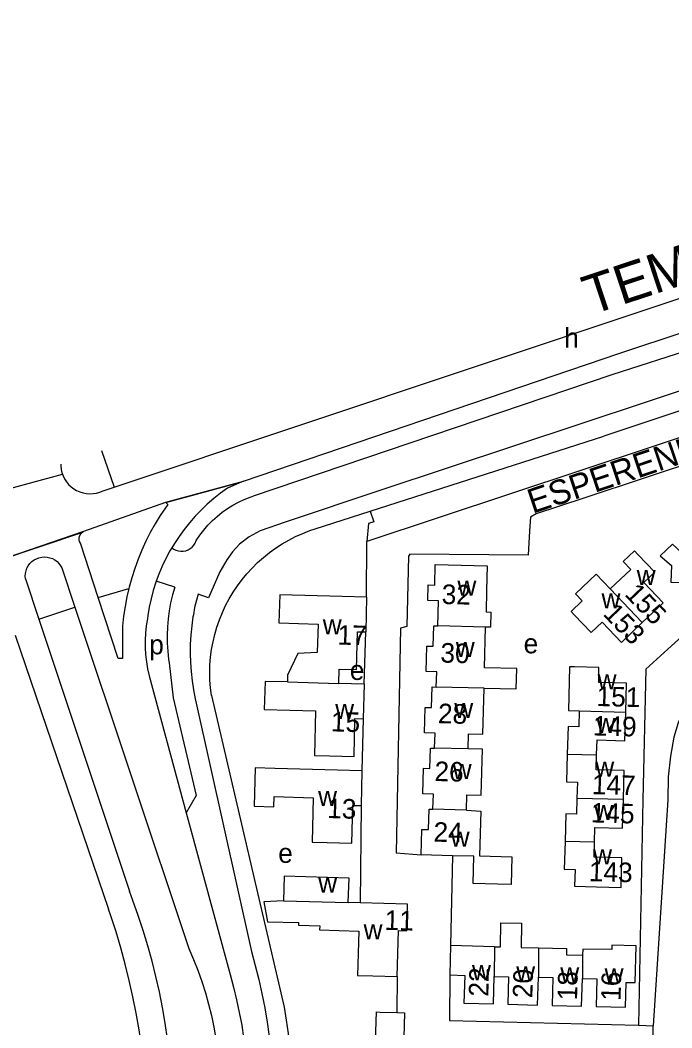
# Model space of a CAD drawing. Extents: x 161936 to 163647, y 386450 to 388633.
# Drawn here: x 162199.4 to 162332.5, y 388398.4 to 388604.3 of the extents above; entities that cross this region are included whole.
import ezdxf

# ---------------------------------------------------------------- set-up
doc = ezdxf.new("R2010")
doc.units = 0
for name, color, linetype in [('BLT_Basislijn', 7, 'Continuous'), ('BLT_Bebouwing', 7, 'Continuous'), ('BLT_Centroide', 7, 'Continuous'), ('BLT_Huisnummer', 7, 'Continuous'), ('BLT_Huisnummer_ tussenligend', 7, 'Continuous'), ('BLT_Onderverdeling_panden', 7, 'Continuous'), ('BLT_Straatnaam', 7, 'Continuous'), ('BLT_Straatnaam_hoofdweg', 7, 'Continuous'), ('BLT_Vlakafsluiter', 7, 'Continuous')]:
    doc.layers.add(name, color=color, linetype=linetype)

msp = doc.modelspace()

# ---------------------------------------------------------------- linework, layer by layer
at = {"layer": 'BLT_Basislijn'}
for p, q in [((162417.3, 388562.99), (162320.24, 388531.86)), ((162320.24, 388531.86), (162247, 388507.07)), ((162270.93, 388504.03), (162318.61, 388519.35)), ((162216.04, 388516.41), (162218.65, 388508.94)), ((162216.15, 388508.1), (162218.65, 388508.94)), ((162273.31, 388508.35), (162253.51, 388501.78)), ((162259.69, 388500.42), (162270.93, 388504.03)), ((162215.37, 388486.34), (162211.74, 388497.46)), ((162270.18, 388486.44), (162270.23, 388497.84)), ((162207.93, 388492.42), (162210.6, 388484.42)), ((162200.52, 388490.16), (162203.24, 388481.96)), ((162215.37, 388486.34), (162221.63, 388488.23)), ((162230.98, 388488.5), (162227.22, 388489.69)), ((162203.24, 388481.96), (162210.6, 388484.42)), ((162210.6, 388484.42), (162233.9, 388414.65)), ((162203.24, 388481.96), (162221.73, 388426.34)), ((162198.38, 388478.67), (162217.49, 388422.65)), ((162269.7, 388468.68), (162270.01, 388479.33)), ((162229.85, 388473.02), (162230.69, 388465.88)), ((162225.77, 388470.37), (162233.35, 388442.37)), ((162238.48, 388466.33), (162253.34, 388402.63)), ((162235.4, 388464.79), (162246.64, 388414.02)), ((162269.5, 388461.6), (162269.23, 388450.96)), ((162331.69, 388444.99), (162328.69, 388398.84)), ((162269.06, 388443.84), (162268.87, 388423.97)), ((162233.35, 388442.37), (162242.29, 388409.3)), ((162287.74, 388433.61), (162287.33, 388415.23)), ((162276.44, 388408.91), (162276.34, 388401.56)), ((162325.67, 388399), (162328.69, 388398.84)), ((162328.55, 388389.95), (162328.69, 388398.84))]:
    msp.add_line(p, q, dxfattribs=at)
for points in [[(162245.01, 388510.15), (162321.69, 388536.21), (162403.77, 388563.49), (162420.12, 388569.86), (162440.47, 388580.95), (162451.05, 388585.71), (162460.59, 388590.61), (162470.65, 388596.83), (162481.66, 388604.34)], [(162218.65, 388508.94), (162366.2, 388558.22), (162401.08, 388569.64)], [(162447.07, 388563.49), (162414.11, 388552.89), (162414.48, 388551.26), (162318.61, 388519.35)], [(162408.33, 388553.19), (162273.31, 388508.35)], [(162420.21, 388534.15), (162419.72, 388536.07), (162387.4, 388536.71), (162270.23, 388497.84)], [(162351.5, 388518.91), (162314.5, 388506.68)], [(162207.72, 388513.6), (162207.72, 388513.24), (162207.8, 388512.55), (162207.96, 388511.88), (162208.07, 388511.55)], [(162208.07, 388511.55), (162208.19, 388511.23), (162208.5, 388510.61), (162208.87, 388510.02), (162209.32, 388509.49), (162209.81, 388509.01), (162210.37, 388508.59), (162210.96, 388508.24), (162211.59, 388507.96), (162212.26, 388507.76), (162212.93, 388507.63), (162213.62, 388507.58), (162214.32, 388507.61), (162215, 388507.72), (162215.67, 388507.91), (162216.15, 388508.1)], [(162244.71, 388510.02), (162241.74, 388508.7), (162240.32, 388507.68), (162238.95, 388506.59), (162237.63, 388505.44), (162236.36, 388504.23), (162235.14, 388502.96), (162233.99, 388501.64), (162232.9, 388500.27), (162231.87, 388498.85), (162230.91, 388497.38), (162230.39, 388496.51)], [(162245.01, 388510.15), (162244.71, 388510.02)], [(162235.4, 388498), (162236.13, 388499.09), (162236.92, 388500.14), (162237.77, 388501.13), (162238.68, 388502.07), (162239.65, 388502.95), (162240.67, 388503.77), (162241.74, 388504.53), (162242.85, 388505.22), (162244, 388505.84), (162245.19, 388506.39), (162246.41, 388506.87), (162247, 388507.07)], [(162314.5, 388506.68), (162304.79, 388503.47), (162303.65, 388502.79), (162303.44, 388500), (162303.15, 388495.01), (162279.02, 388495.2), (162278.7, 388494.79), (162278.38, 388480.46), (162277.09, 388480.11), (162276.21, 388434.19), (162281.34, 388433.78)], [(162212.45, 388499.89), (162229.15, 388505.84)], [(162229.19, 388505.8), (162229.6, 388505.38), (162228.02, 388503.12)], [(162229.15, 388505.84), (162229.19, 388505.8)], [(162228.02, 388503.12), (162226.98, 388501.41), (162226, 388499.66), (162225.1, 388497.86), (162224.27, 388496.04), (162223.51, 388494.18), (162222.82, 388492.3), (162222.21, 388490.38), (162221.68, 388488.45), (162221.63, 388488.23)], [(162270.93, 388504.03), (162271.64, 388501.83), (162270.59, 388501.51), (162270.23, 388497.84)], [(162253.51, 388501.78), (162248.43, 388500), (162246.16, 388498.78), (162244.19, 388497.26), (162242.82, 388495.7), (162241.65, 388494.04), (162240.17, 388491.59), (162237.87, 388486.3), (162235.77, 388487.08), (162235.41, 388485.84), (162235.06, 388484.35), (162234.79, 388482.84), (162234.72, 388482.39)], [(162211.74, 388497.46), (162211.57, 388497.78), (162211.47, 388498.13), (162211.46, 388498.49), (162211.52, 388498.84), (162211.66, 388499.18), (162211.87, 388499.47), (162212.14, 388499.71), (162212.21, 388499.75)], [(162212.21, 388499.75), (162212.45, 388499.89)], [(162238.48, 388466.33), (162238.29, 388467.89), (162238.18, 388469.46), (162238.14, 388471.03), (162238.19, 388472.61), (162238.32, 388474.18), (162238.52, 388475.74), (162238.81, 388477.29), (162239.17, 388478.82), (162239.61, 388480.33), (162240.13, 388481.82), (162240.72, 388483.28), (162241.38, 388484.7), (162242.12, 388486.09), (162242.93, 388487.45), (162243.8, 388488.75), (162244.74, 388490.02), (162245.74, 388491.23), (162246.8, 388492.39), (162247.92, 388493.5), (162249.1, 388494.55), (162250.33, 388495.53), (162251.6, 388496.46), (162252.92, 388497.31), (162254.28, 388498.1), (162255.68, 388498.82), (162257.12, 388499.47), (162258.59, 388500.04), (162259.69, 388500.42)], [(162230.39, 388496.51), (162230.01, 388495.88), (162229.19, 388494.33), (162228.43, 388492.75), (162227.75, 388491.13), (162227.22, 388489.69)], [(162230.39, 388496.51), (162230.8, 388496.23), (162231.25, 388496.02), (162231.74, 388495.88), (162232.24, 388495.82), (162232.74, 388495.84), (162233.24, 388495.93), (162233.71, 388496.11), (162234.15, 388496.36), (162234.55, 388496.67), (162234.89, 388497.04), (162235.17, 388497.46), (162235.4, 388498)], [(162200.52, 388490.16), (162200.48, 388490.72), (162200.51, 388491.28), (162200.63, 388491.82), (162200.82, 388492.35), (162201.09, 388492.84), (162201.42, 388493.29), (162201.81, 388493.69), (162202.26, 388494.03), (162202.75, 388494.3), (162203.27, 388494.49), (162203.82, 388494.62), (162204.37, 388494.66), (162204.93, 388494.62), (162205.48, 388494.5), (162206, 388494.31), (162206.5, 388494.05), (162206.95, 388493.71), (162207.34, 388493.32), (162207.68, 388492.87), (162207.93, 388492.42)], [(162221.63, 388488.23), (162221.23, 388486.49), (162220.85, 388484.52), (162220.55, 388482.54), (162220.33, 388480.49)], [(162227.22, 388489.69), (162227.15, 388489.49), (162226.62, 388487.82), (162226.16, 388486.12), (162225.79, 388484.41), (162225.49, 388482.68), (162225.4, 388482.02)], [(162230.98, 388488.5), (162230.52, 388486.9), (162230.15, 388485.29), (162229.85, 388483.65), (162229.64, 388482.01), (162229.5, 388480.35), (162229.44, 388478.69), (162229.46, 388477.03), (162229.57, 388475.37), (162229.75, 388473.72), (162229.85, 388473.02)], [(162220.33, 388480.49), (162220.33, 388473.93), (162219.43, 388473.93), (162215.37, 388486.34)], [(162225.4, 388482.02), (162225.16, 388480.57), (162225.01, 388479.11), (162224.94, 388477.64), (162224.95, 388476.17), (162225.04, 388474.7), (162225.2, 388473.24), (162225.45, 388471.79), (162225.77, 388470.37)], [(162234.72, 388482.39), (162234.45, 388480.55), (162234.27, 388478.69), (162234.16, 388476.82), (162234.13, 388474.95), (162234.18, 388473.09), (162234.32, 388471.22), (162234.53, 388469.36), (162234.82, 388467.52), (162235.19, 388465.69), (162235.4, 388464.79)], [(162363.21, 388479.21), (162336.14, 388479.83), (162331.7, 388475.81)], [(162331.7, 388475.81), (162327.16, 388471.71), (162326.61, 388445.04)], [(162363.89, 388473.57), (162351.28, 388473.57), (162346.78, 388472.82), (162343.16, 388471.29), (162339.91, 388468.94), (162337.35, 388466.34), (162335.18, 388463.53), (162333.83, 388460.74), (162332.91, 388457.81), (162332.21, 388453.97), (162331.73, 388449.73), (162331.69, 388444.99)], [(162230.69, 388465.88), (162235.4, 388445.93), (162233.35, 388442.37)], [(162326.61, 388445.04), (162325.67, 388399)], [(162229.94, 388392.92), (162229.54, 388396.14), (162229.06, 388399.36), (162228.51, 388402.57), (162227.87, 388405.76), (162227.16, 388408.93), (162226.37, 388412.09), (162225.5, 388415.22), (162224.55, 388418.33), (162223.53, 388421.42), (162222.43, 388424.48), (162221.73, 388426.34)], [(162224.63, 388391.27), (162224.21, 388394.66), (162223.7, 388398.05), (162223.11, 388401.43), (162222.45, 388404.79), (162221.7, 388408.13), (162220.88, 388411.46), (162219.98, 388414.76), (162219.01, 388418.05), (162217.95, 388421.31), (162217.49, 388422.65)], [(162233.9, 388414.65), (162234.85, 388412.43), (162235.73, 388410.19), (162236.53, 388407.91), (162237.25, 388405.61), (162237.9, 388403.28), (162238.47, 388400.94), (162238.97, 388398.58), (162239.38, 388396.2)], [(162246.64, 388414.02), (162247.44, 388411.17), (162248.16, 388408.31), (162248.8, 388405.42), (162249.37, 388402.52), (162249.86, 388399.6), (162250.27, 388396.67), (162250.59, 388393.74), (162250.84, 388390.79), (162251.01, 388387.84), (162251.1, 388384.88), (162251.11, 388381.93), (162251.04, 388378.97), (162250.99, 388377.76)], [(162242.29, 388409.3), (162243, 388406.76), (162243.63, 388404.18), (162244.18, 388401.6), (162244.66, 388398.99), (162245.05, 388396.38), (162245.37, 388393.75), (162245.61, 388391.11), (162245.77, 388388.47), (162245.84, 388385.82), (162245.84, 388383.18), (162245.76, 388380.53), (162245.6, 388377.89), (162245.37, 388375.4)], [(162287.17, 388409.25), (162287.1, 388399.94), (162325.67, 388399)], [(162253.34, 388402.63), (162253.78, 388399.98), (162254.15, 388397.31), (162254.43, 388394.64), (162254.63, 388391.95), (162254.75, 388389.27), (162254.79, 388386.58), (162254.78, 388385.78)]]:
    msp.add_lwpolyline(points, dxfattribs=at)
at = {"layer": 'BLT_Bebouwing'}
for p, q in [((162270.18, 388486.44), (162270.01, 388479.33)), ((162269.7, 388468.68), (162269.5, 388461.6)), ((162269.23, 388450.96), (162269.06, 388443.84)), ((162287.74, 388433.61), (162281.34, 388433.78)), ((162287.33, 388415.23), (162287.17, 388409.25)), ((162296.09, 388403.32), (162296.23, 388408.91)), ((162305.09, 388403.09), (162305.25, 388408.79)), ((162314.08, 388402.87), (162314.24, 388408.54))]:
    msp.add_line(p, q, dxfattribs=at)
for points in [[(162336.97, 388495.39), (162334.56, 388495.46), (162332.67, 388497.29), (162330.13, 388494.88), (162332.41, 388492.92), (162332.32, 388489.52), (162336.82, 388489.4)], [(162326.47, 388481.24), (162330.74, 388485.29), (162326.78, 388489.42), (162329, 388491.53), (162325.56, 388495.16), (162324.87, 388495.88), (162322.59, 388493.7), (162324.11, 388492.1), (162319.92, 388488.11)], [(162284.71, 388480.6), (162284.87, 388485.69), (162282.68, 388485.74), (162282.76, 388488.96), (162284.08, 388488.92), (162284.19, 388493.13), (162294.8, 388492.83), (162294.67, 388487.83), (162294.56, 388483.43), (162295.54, 388483.4), (162295.46, 388480.3), (162294.47, 388480.33)], [(162319.92, 388488.11), (162317.03, 388491.14), (162312.83, 388487.15), (162314.21, 388485.7), (162311.93, 388483.53), (162312.59, 388482.83), (162316.04, 388479.21), (162318.25, 388481.32), (162322.2, 388477.18), (162326.47, 388481.24)], [(162270.18, 388486.44), (162265.18, 388486.57), (162252.43, 388486.9), (162252.27, 388481.17), (162260.26, 388480.95), (162260.1, 388475.12), (162256.15, 388474.91), (162254.04, 388470.49), (162254, 388469.11)], [(162284.39, 388468.07), (162284.49, 388471.19), (162282.32, 388471.26), (162282.44, 388476.45), (162283.76, 388476.41), (162283.9, 388480.61), (162284.71, 388480.6)], [(162294.15, 388467.85), (162300.74, 388467.69), (162300.85, 388471.84), (162294.26, 388472), (162294.47, 388480.33)], [(162264.5, 388468.82), (162264.6, 388471.74), (162268.09, 388471.65), (162268.31, 388479.38), (162270.01, 388479.33)], [(162323.08, 388462.96), (162323.23, 388468.85), (162317.58, 388469.02), (162317.6, 388472.03), (162312.6, 388472.17), (162311.63, 388472.2), (162311.39, 388463.26), (162313.59, 388463.21)], [(162254, 388469.11), (162249.44, 388469.23), (162249.28, 388463.47), (162259.76, 388463.18), (162259.51, 388454.11), (162262.61, 388454.03), (162267.61, 388453.89), (162267.8, 388461.64), (162269.5, 388461.6)], [(162269.7, 388468.68), (162264.5, 388468.82)], [(162284.04, 388455.61), (162284.14, 388458.64), (162282, 388458.71), (162282.12, 388463.92), (162283.45, 388463.88), (162283.57, 388468.1), (162284.39, 388468.07)], [(162290.92, 388455.43), (162291, 388458.5), (162293.9, 388458.42), (162294.15, 388467.85)], [(162313.59, 388463.21), (162313.5, 388459.94), (162311.31, 388460), (162311.16, 388454.36)], [(162317.14, 388454.2), (162317.23, 388457.26), (162322.93, 388457.1), (162323.08, 388462.96)], [(162283.73, 388443.11), (162283.82, 388446.21), (162281.67, 388446.28), (162281.8, 388451.46), (162283.11, 388451.42), (162283.24, 388455.59), (162284.04, 388455.61)], [(162290.59, 388442.93), (162290.67, 388446.05), (162293.59, 388445.97), (162293.82, 388455.35), (162290.92, 388455.43)], [(162311.16, 388454.36), (162311.01, 388448.71), (162313.21, 388448.65), (162313.12, 388445.39)], [(162322.61, 388445.14), (162322.76, 388451.01), (162317.06, 388451.17), (162317.14, 388454.2)], [(162269.23, 388450.96), (162264.23, 388451.1), (162251.45, 388451.45), (162247.44, 388451.56), (162247.22, 388443.73), (162251.23, 388443.61), (162251.29, 388445.68), (162259.29, 388445.46), (162259.05, 388436.39), (162262.15, 388436.31), (162267.15, 388436.17), (162267.36, 388443.89), (162269.06, 388443.84)], [(162313.12, 388445.39), (162313.04, 388442.12), (162310.84, 388442.18), (162310.69, 388436.49)], [(162316.7, 388436.35), (162316.77, 388439.39), (162322.45, 388439.26), (162322.61, 388445.14)], [(162281.34, 388433.78), (162281.47, 388438.99), (162282.79, 388438.95), (162282.93, 388443.14), (162283.73, 388443.11)], [(162290.59, 388442.93), (162293.49, 388442.7), (162293.25, 388433.57), (162299.81, 388433.38), (162299.71, 388427.71), (162296.92, 388427.79), (162291.92, 388427.92), (162292.08, 388433.49), (162287.74, 388433.61)], [(162310.69, 388436.49), (162310.55, 388430.86), (162312.74, 388430.81), (162312.65, 388427.37), (162317.13, 388427.25), (162322.13, 388427.11), (162322.31, 388433.18), (162316.63, 388433.31), (162316.7, 388436.35)], [(162266.43, 388424.04), (162266.58, 388429.03), (162253.33, 388429.4), (162253.19, 388424.41)], [(162253.19, 388424.41), (162249.18, 388424.19), (162249.95, 388420.12), (162256.26, 388419.94), (162256.25, 388419.4), (162260.61, 388419.28), (162260.58, 388418.43), (162268.59, 388418.19), (162268.32, 388409.12), (162271.44, 388409.04), (162276.44, 388408.91)], [(162268.87, 388423.97), (162266.43, 388424.04)], [(162276.44, 388408.91), (162276.67, 388418.32), (162278.38, 388418.27), (162278.53, 388423.7), (162268.87, 388423.97)], [(162296.3, 388415), (162297.49, 388414.97), (162297.61, 388419.9), (162301.83, 388419.8), (162301.71, 388414.87), (162305.28, 388414.78)], [(162296.3, 388415), (162287.33, 388415.23)], [(162305.28, 388414.78), (162311.01, 388414.62), (162310.98, 388413.35), (162314.28, 388413.28)], [(162314.24, 388408.54), (162317.18, 388408.45), (162317.02, 388402.78), (162323.07, 388402.63), (162323.2, 388407.73), (162325, 388407.68), (162325.2, 388415.18), (162320.25, 388415.31), (162320.22, 388414.41), (162314.31, 388414.54), (162314.28, 388413.28)], [(162287.17, 388409.25), (162290.22, 388409.16), (162290.05, 388403.47), (162296.09, 388403.32)], [(162296.23, 388408.91), (162299.12, 388408.84), (162298.99, 388403.24), (162305.09, 388403.09)], [(162305.25, 388408.79), (162308.2, 388408.71), (162308.04, 388403.01), (162314.08, 388402.87)], [(162262.65, 388385.85), (162262.79, 388390.85), (162262.88, 388393.95), (162271.95, 388393.69), (162272.18, 388401.69), (162272.93, 388401.67), (162276.34, 388401.56)], [(162276.34, 388401.56), (162277.93, 388401.51), (162277.42, 388383.73), (162270.33, 388383.95), (162270.37, 388385.65), (162262.65, 388385.85)]]:
    msp.add_lwpolyline(points, dxfattribs=at)
at = {"layer": 'BLT_Onderverdeling_panden'}
for p, q in [((162319.92, 388488.11), (162326.47, 388481.24)), ((162294.47, 388480.33), (162284.71, 388480.6)), ((162254, 388469.11), (162264.5, 388468.82)), ((162294.15, 388467.85), (162284.39, 388468.07)), ((162313.59, 388463.21), (162323.08, 388462.96)), ((162290.92, 388455.43), (162284.04, 388455.61)), ((162311.16, 388454.36), (162317.14, 388454.2)), ((162313.12, 388445.39), (162322.61, 388445.14)), ((162290.59, 388442.93), (162283.73, 388443.11)), ((162316.7, 388436.35), (162310.69, 388436.49)), ((162253.19, 388424.41), (162266.43, 388424.04)), ((162296.3, 388415), (162296.23, 388408.91)), ((162305.28, 388414.78), (162305.25, 388408.79)), ((162314.28, 388413.28), (162314.24, 388408.54))]:
    msp.add_line(p, q, dxfattribs=at)
at = {"layer": 'BLT_Vlakafsluiter'}
for p, q in [((162189.46, 388506.53), (162208.07, 388511.55)), ((162229.15, 388505.84), (162245.01, 388510.15)), ((162229.19, 388505.8), (162244.71, 388510.02)), ((162181.28, 388489.3), (162212.45, 388499.89)), ((162181.55, 388489.34), (162212.21, 388499.75))]:
    msp.add_line(p, q, dxfattribs=at)

# ---------------------------------------------------------------- texts
at = {"layer": 'BLT_Centroide'}
for s, p in [('h', (162310.53, 388537.45)), ('w', (162325.33, 388488.92)), ('w', (162288.72, 388486.75)), ('w', (162318.14, 388484.16)), ('w', (162261.22, 388478.83)), ('p', (162225.79, 388474.75)), ('e', (162302.24, 388474.96)), ('w', (162288.39, 388474.23)), ('e', (162266.75, 388469.52)), ('w', (162317.35, 388467.59)), ('w', (162263.76, 388461.56)), ('w', (162288.08, 388461.75)), ('w', (162317.12, 388458.69)), ('w', (162287.75, 388449.25)), ('w', (162316.88, 388449.75)), ('w', (162260.27, 388443.78)), ('w', (162316.66, 388440.88)), ('w', (162287.34, 388435.44)), ('e', (162252.13, 388432.14)), ('w', (162316.42, 388431.81)), ('w', (162260.29, 388426.05)), ('w', (162269.56, 388416.52)), ('w', (162291.7, 388408.17)), ('w', (162300.73, 388407.94)), ('w', (162309.73, 388407.72)), ('w', (162318.78, 388407.5))]:
    msp.add_text(s, height=4, dxfattribs=at).set_placement(p)
at = {"layer": 'BLT_Huisnummer'}
for s, rotation, p in [('32', 358.4552, (162285.47, 388485.06)), ('155', 313.6378, (162322.69, 388486.92)), ('153', 313.6546, (162318.28, 388482.88)), ('17', 358.5228, (162264.21, 388476.75)), ('151', 358.5099, (162317.1, 388464.2)), ('28', 358.4593, (162284.71, 388460.7)), ('15', 358.4413, (162262.85, 388459.02)), ('147', 358.5083, (162316.14, 388446.19)), ('13', 358.4413, (162262.09, 388441.31)), ('24', 358.6739, (162283.8, 388436.48)), ('143', 358.4299, (162315.53, 388428.41)), ('11', 358.5138, (162273.81, 388418.46)), ('22', 88.6702, (162295.03, 388404.77)), ('16', 88.491, (162322.03, 388403.91))]:
    msp.add_text(s, height=4, rotation=rotation, dxfattribs=at).set_placement(p)
at = {"layer": 'BLT_Huisnummer_ tussenligend'}
for s, rotation, p in [('30', 358.4527, (162285.21, 388473.09)), ('149', 358.5083, (162316.34, 388458.19)), ('26', 358.6739, (162284, 388448.87)), ('145', 358.4299, (162315.92, 388440.42)), ('20', 88.3921, (162304.01, 388404.46)), ('18', 88.491, (162313.14, 388404.02))]:
    msp.add_text(s, height=4, rotation=rotation, dxfattribs=at).set_placement(p)
at = {"layer": 'BLT_Straatnaam'}
msp.add_text('ESPERENKAMP', height=4.9999, rotation=18.5601, dxfattribs=at).set_placement((162304.06, 388503.46))
at = {"layer": 'BLT_Straatnaam_hoofdweg'}
msp.add_text('TEMPELLAAN', height=8, rotation=18.2315, dxfattribs=at).set_placement((162316, 388544.04))

doc.saveas('drawing.dxf')
